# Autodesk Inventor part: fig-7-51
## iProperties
Shininess: 77.0
Length Units: 11269
Angle Units: 11279
Time Units: 11290
Mass Units: 11283
Length Display Precision: 3
Angle Display Precision: 2
Created: 2002-01
Part Number: fig-7-51
Document SubType Name: Modeling
Designer: ***
Density: 0.0
Volumn: 0.0
Area: 0.0
PropertySet Name: Model Information
Control State: 0
Master: False
Checked Out: False
Author: ***
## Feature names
1. Extrusion2
2. FaceDraft7
